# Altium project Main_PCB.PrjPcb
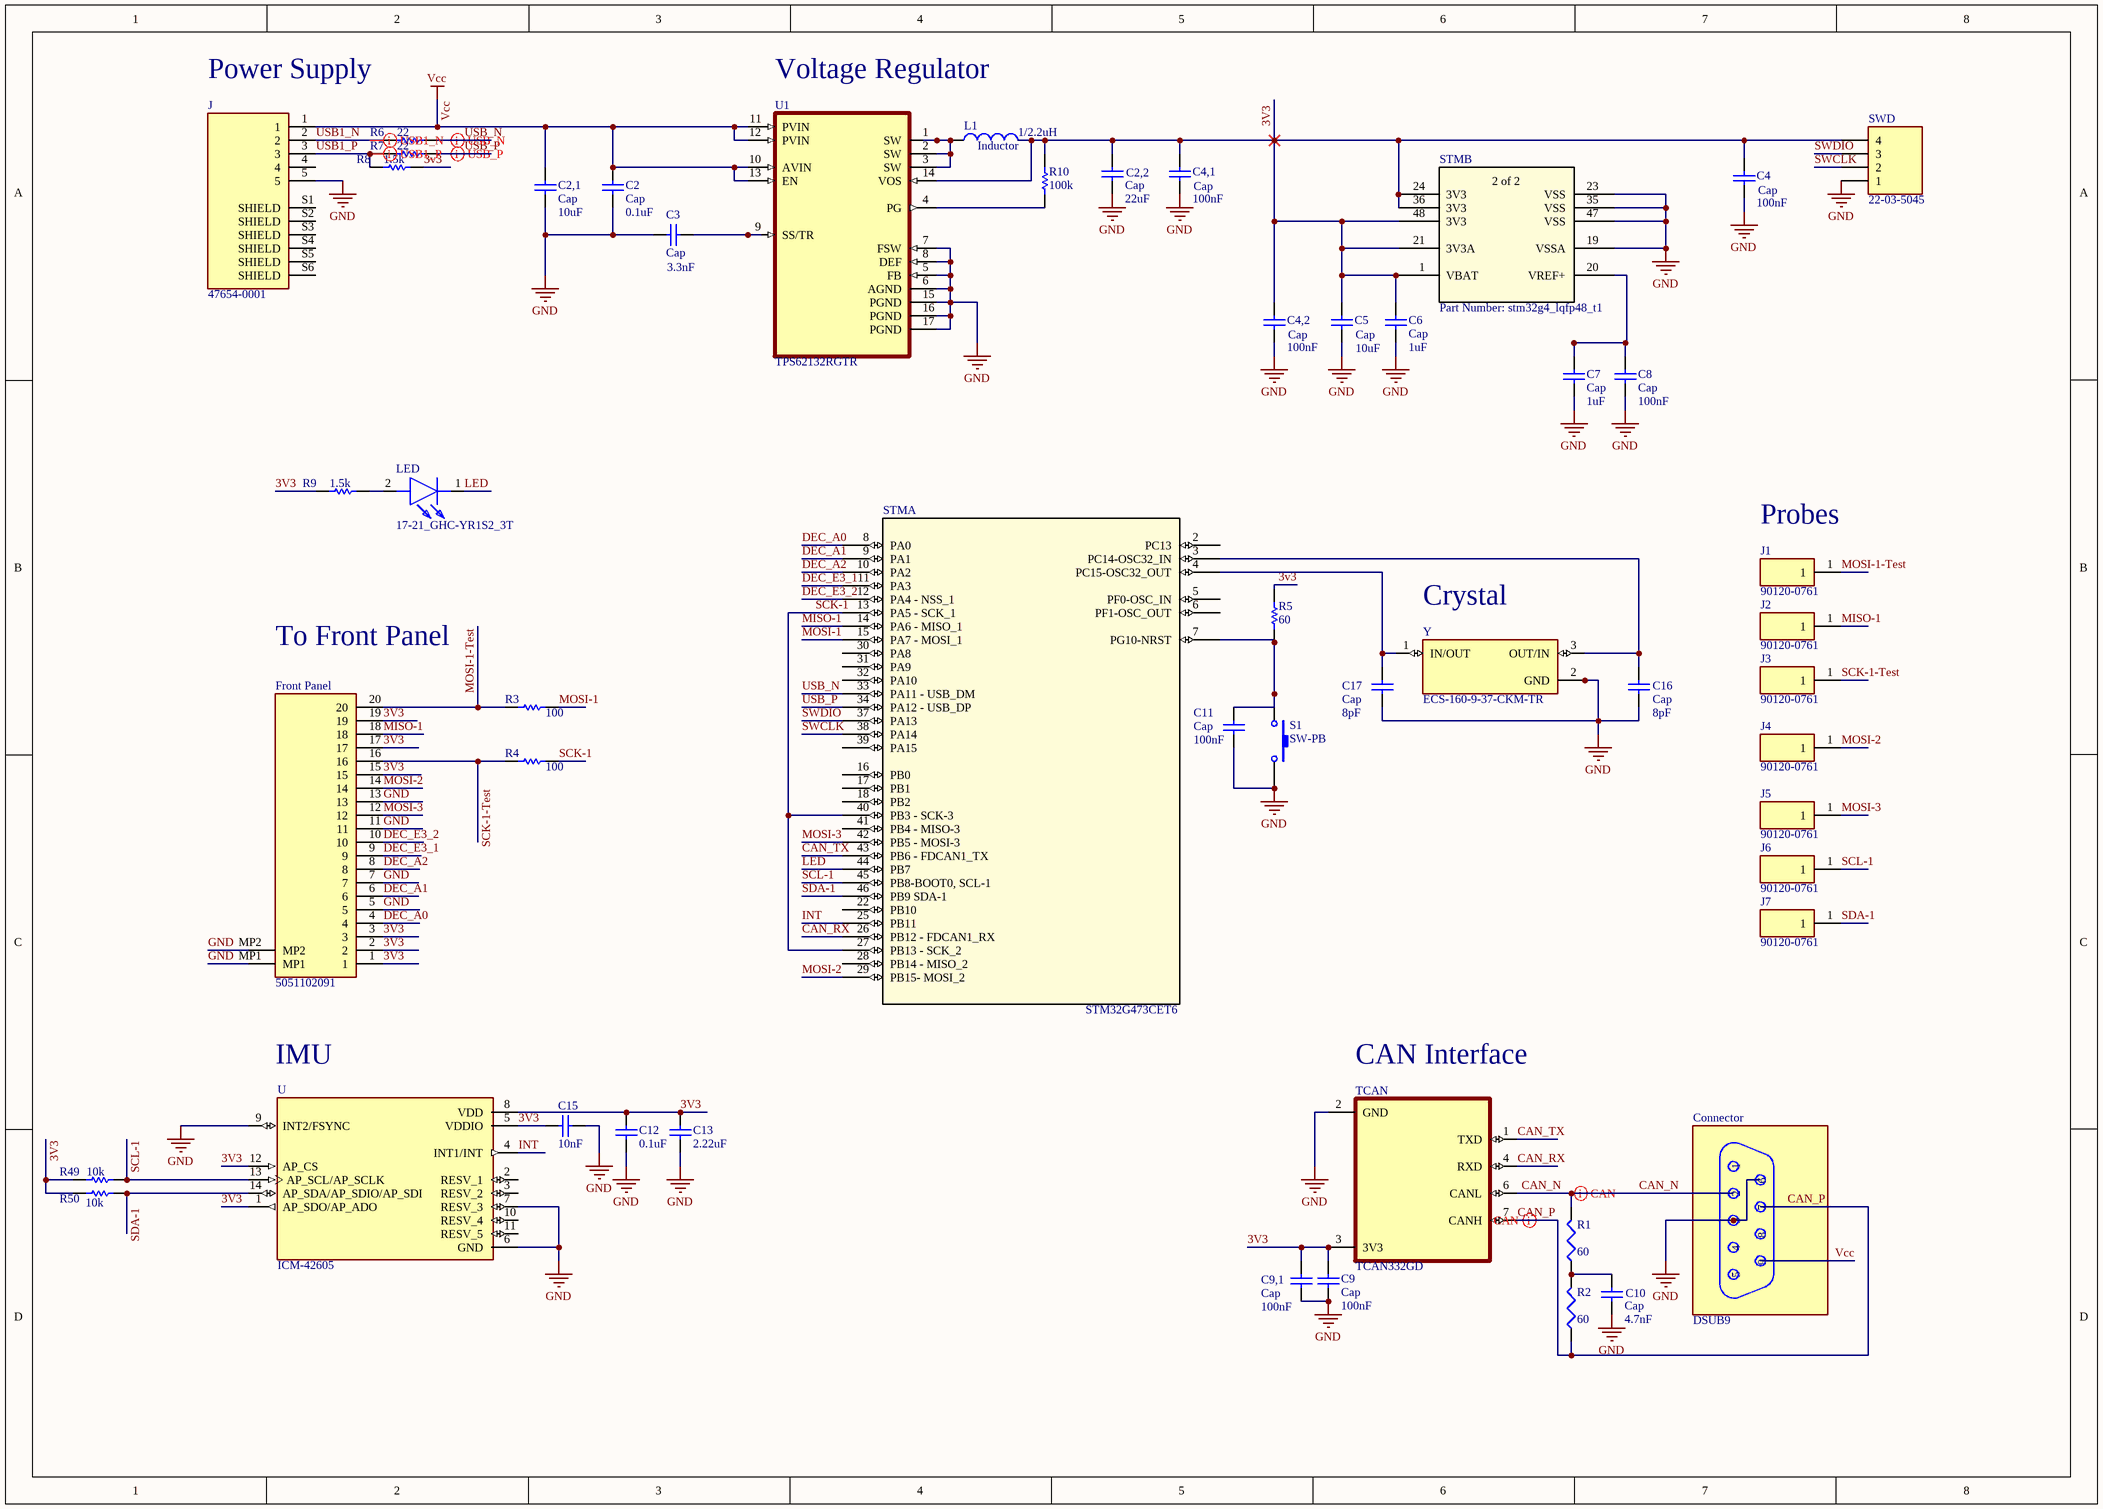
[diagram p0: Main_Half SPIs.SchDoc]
1 sheet, 51 parts. Net scope: global (net labels, ports and power ports of the same name join across sheets).
Board file: Main_Half SPIs.PcbDoc

## Sheet Main_Half SPIs.SchDoc
size A3

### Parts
C2  Cap  value 0.1uF  [INDC2012X55N]
C2,1  Cap  value 10uF  [INDC2012X55N]
C2,2  Cap  value 22uF  [INDC2012X55N]
C3  Cap  value 3.3nF  [INDC2012X55N]
C4  Cap  value 100nF  [CAPC1608X90N]
C4,1  Cap  value 100nF  [CAPC1608X90N]
C4,2  Cap  value 100nF  [CAPC1608X90N]
C5  Cap  value 10uF  [CAPC1608X90N]
C6  Cap  value 1uF  [CAPC1608X90N]
C7  Cap  value 1uF  [CAPC1608X90N]
C8  Cap  value 100nF  [CAPC1608X90N]
C9  Cap  value 100nF  [CAPC1608X90N]
C9,1  Cap  value 100nF  [CAPC1608X90N]
C10  Cap  value 4.7nF  [CAPC1608X90N]
C11  Cap  value 100nF  [CAPC1608X90N]
C12  value 0.1uF  [CAPC1608X90N]  (hidden comment: Cap)
C13  value 2.22uF  [CAPC1608X90N]  (hidden comment: Cap)
C15  value 10nF  [CAPC1608X90N]  (hidden comment: Cap)
C16  Cap  value 8pF  [CAPC1608X90N]
C17  Cap  value 8pF  [CAPC1608X90N]
Connector  DSUB9  [23018431]
Front_Panel  5051102091  [5051102091]
J  47654-0001  [USB_Conector]
J1  90120-0761  [HDRV1W90P0X254_1X1_232X249X560P]
J2  90120-0761  [HDRV1W90P0X254_1X1_232X249X560P]
J3  90120-0761  [HDRV1W90P0X254_1X1_232X249X560P]
J4  90120-0761  [HDRV1W90P0X254_1X1_232X249X560P]
J5  90120-0761  [HDRV1W90P0X254_1X1_232X249X560P]
J6  90120-0761  [HDRV1W90P0X254_1X1_232X249X560P]
J7  90120-0761  [HDRV1W90P0X254_1X1_232X249X560P]
L1  Inductor  value 1/2.2uH  [INDC2012X55N]
LED  17-21_GHC-YR1S2_3T  [LEDM2012X110N]
R1  value 60  [J1-0603]  (hidden comment: Res3)
R2  value 60  [J1-0603]  (hidden comment: Res3)
R3  value 100  [CAPC1608X90N]  (hidden comment: Res)
R4  value 100  [CAPC1608X90N]  (hidden comment: Res)
R5  value 60  [CAPC1608X90N]  (hidden comment: Res)
R6  value 22  [CAPC1608X90N]  (hidden comment: Res)
R7  value 22  [CAPC1608X90N]  (hidden comment: Res)
R8  value 1.5k  [CAPC1608X90N]  (hidden comment: Res)
R9  value 1.5k  [CAPC1608X90N]  (hidden comment: Res)
R10  value 100k  [CAPC1608X90N]  (hidden comment: Res)
R49  value 10k  [CAPC1608X90N]  (hidden comment: Res)
R50  value 10k  [CAPC1608X90N]  (hidden comment: Res)
S1  SW-PB  [SPST-2]
STM  STM32G473CET6  [QFP50P900X900X160-48N]  (parts A,B of 2)
SWD  22-03-5045  [MOLEX_22-03-5045]
TCAN  TCAN332GD  [SOT65P280X145-8N]
U  ICM-42605  [PQFN50P300X250X97-14N]
U1  TPS62132RGTR  [QFN50P300X300X100-17N]
Y  ECS-160-9-37-CKM-TR  [XTAL_ECS-160-9-37-CKM-TR]

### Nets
GND: C2.2 C2,1.2 C2,2.1 C3.1 C4.2 C4,1.2 C4,2.2 C5.2 C6.2 C7.2 C8.2 C9.2 C9,1.2 C10.2 C11.2 C12.1 C13.2 C15.1 C16.2 C17.2 Connector.3 Connector.6 Front_Panel.5 Front_Panel.7 Front_Panel.11 Front_Panel.13 Front_Panel.MP1 Front_Panel.MP2 J.5 S1.2 STM.19(VSSA) STM.23(VSS) STM.35(VSS) STM.47(VSS) SWD.1 TCAN.2(GND) U.6(GND) U.7(RESV_3) U.9(INT2/FSYNC) U1.5(FB) U1.6(AGND) U1.7(FSW) U1.8(DEF) U1.15(PGND) U1.16(PGND) U1.17(PGND) Y.2(GND) Y.4(GND)
Vcc: C2.1 C2,1.1 Connector.9 J.1 U1.10(AVIN) U1.11(PVIN) U1.12(PVIN) U1.13(EN)
3V3: C2,2.2 C4.1 C4,1.1 C4,2.1 C5.1 C6.1 C9.1 C9,1.1 C12.2 C13.1 C15.2 Front_Panel.1 Front_Panel.2 Front_Panel.3 Front_Panel.15 Front_Panel.17 Front_Panel.19 L1.2 R5.2 R8.1 R9.2 R10.1 R49.2 R50.2 STM.1(VBAT) STM.21(3V3A) STM.24(3V3) STM.36(3V3) STM.48(3V3) SWD.4 TCAN.3(3V3) U.1(AP_SDO/AP_ADO) U.5(VDDIO) U.8(VDD) U.12(AP_CS) U1.14(VOS)
CAN_N: Connector.2 R1.2 TCAN.6(CANL)
CAN_P: Connector.7 R2.1 TCAN.7(CANH)
CAN_RX: STM.26(PB12_-_FDCAN1_RX) TCAN.4(RXD)
CAN_TX: STM.43(PB6_-_FDCAN1_TX) TCAN.1(TXD)
DEC_A0: Front_Panel.4 STM.8(PA0)
DEC_A1: Front_Panel.6 STM.9(PA1)
DEC_A2: Front_Panel.8 STM.10(PA2)
DEC_E3_1: Front_Panel.9 STM.11(PA3)
DEC_E3_2: Front_Panel.10 STM.12(PA4_-_NSS_1)
INT: STM.25(PB11) U.4(INT1/INT)
LED: LED.1(K) STM.44(PB7)
MISO-1: Front_Panel.18 J2.1 STM.14(PA6_-_MISO_1)
MOSI-1: R3.2 STM.15(PA7_-_MOSI_1)
MOSI-1-Test: Front_Panel.20 J1.1 R3.1
MOSI-2: Front_Panel.14 J4.1 STM.29(PB15-_MOSI_2)
MOSI-3: Front_Panel.12 J5.1 STM.42(PB5_-_MOSI-3)
SCK-1: R4.2 STM.13(PA5_-_SCK_1) STM.27(PB13_-_SCK_2) STM.40(PB3_-_SCK-3)
SCK-1-Test: Front_Panel.16 J3.1 R4.1
SCL-1: J6.1 R49.1 STM.45(PB8-BOOT0,_SCL-1) U.13(AP_SCL/AP_SCLK)
SDA-1: J7.1 R50.1 STM.46(PB9_SDA-1) U.14(AP_SDA/AP_SDIO/AP_SDI)
SWCLK: STM.38(PA14) SWD.2
SWDIO: STM.37(PA13) SWD.3
USB1_N: J.2 R6.2
USB1_P: J.3 R7.2 R8.2
USB_N: R6.1 STM.33(PA11_-_USB_DM)
USB_P: R7.1 STM.34(PA12_-_USB_DP)
NetC3_2: C3.2 U1.9(SS/TR)
NetC7_1: C7.1 C8.1 STM.20(VREF+)
NetC10_1: C10.1 R1.1 R2.2
NetC11_1: C11.1 R5.1 S1.1 STM.7(PG10-NRST)
NetC16_1: C16.1 STM.3(PC14-OSC32_IN) Y.3(OUT/IN)
NetC17_1: C17.1 STM.4(PC15-OSC32_OUT) Y.1(IN/OUT)
NetL1_1: L1.1 U1.1(SW) U1.2(SW) U1.3(SW)
NetLED_2: LED.2(A) R9.1
NetR10_2: R10.2 U1.4(PG)

Not connected (* = marked no-connect by the designer): Connector 1 4 5 8; J 4 S1(SHIELD) S2(SHIELD) S3(SHIELD) S4(SHIELD) S5(SHIELD) S6(SHIELD); STM 2(PC13) 5(PF0-OSC_IN) 6(PF1-OSC_OUT) 16(PB0) 17(PB1) 18(PB2) 22(PB10) 28(PB14_-_MISO_2) 30(PA8) 31(PA9) 32(PA10) 39(PA15) 41(PB4_-_MISO-3); U 2(RESV_1) 3(RESV_2) 10(RESV_4) 11(RESV_5)

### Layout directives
differential pair: CAN_N, CAN_P, USB1_N, USB1_P, USB_N, USB_P

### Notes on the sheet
- Power Supply
- Voltage Regulator
- (near J1) Probes
- To Front Panel
- (near Y) Crystal
- (near U) IMU
- (near TCAN) CAN Interface

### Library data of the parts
C2 C2,1 C2,2 C3 C4 C4,1 C4,2 C5-C9 C9,1 C10-C13 C15-C17 = Cap: Capacitor
Connector = DSUB9: Connector Cap _Cover_, Screen For D-Sub Connectors, Female; MF: Assmann WSW
Front_Panel = 5051102091: Connector; Manufacturer_Name: Molex
J = 10118194-0001LF: USB - micro B USB 2.0 Receptacle Connector 5 Position Surface Mount, Right Angle; Through Hole; MF: Amphenol ICC
J1-J7 = 90120-0761: Connector; Manufacturer_Name: Molex
L1 = Inductor: Code_IEC: 1005
LED = 17-21_GHC-YR1S2_3T: LED; Manufacturer_Name: Everlight; Manufacturer_Part_Number: 17-21/GHC-YR1S2/3T
R1 R2 = Res3: Resistor
R3-R10 R49 R50 = Res1: Resistor
S1 = SW-PB: Switch
STM = STM32G4_LQFP48_T: No Description Available; Manufacturer_Part_Number: stm32g4_lqfp48_t1; Built_By: EMA_Jessica; Vendor: STMicroelectronics
SWD = 22-03-5045: Connector Header Through Hole 4 position 0.098 _2.50mm_; MF: Molex; MP: 22035045
TCAN = TCAN332GD: 3.3-V CAN Transceivers with CAN FD (Flexible Data Rate) 8-SOIC -40 to 125; MF: Texas Instruments
U = ICM-42605: Accelerometer, Gyroscope, 6 Axis Sensor IÂ²C, I3Câ„ , SPI Output; MF: TDK InvenSense
Y = ECS-160-9-37-CKM-TR: 16MHz Â±10ppm Crystal 9pF 100 Ohms 4-SMD, No Lead; MF: ECS Inc.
